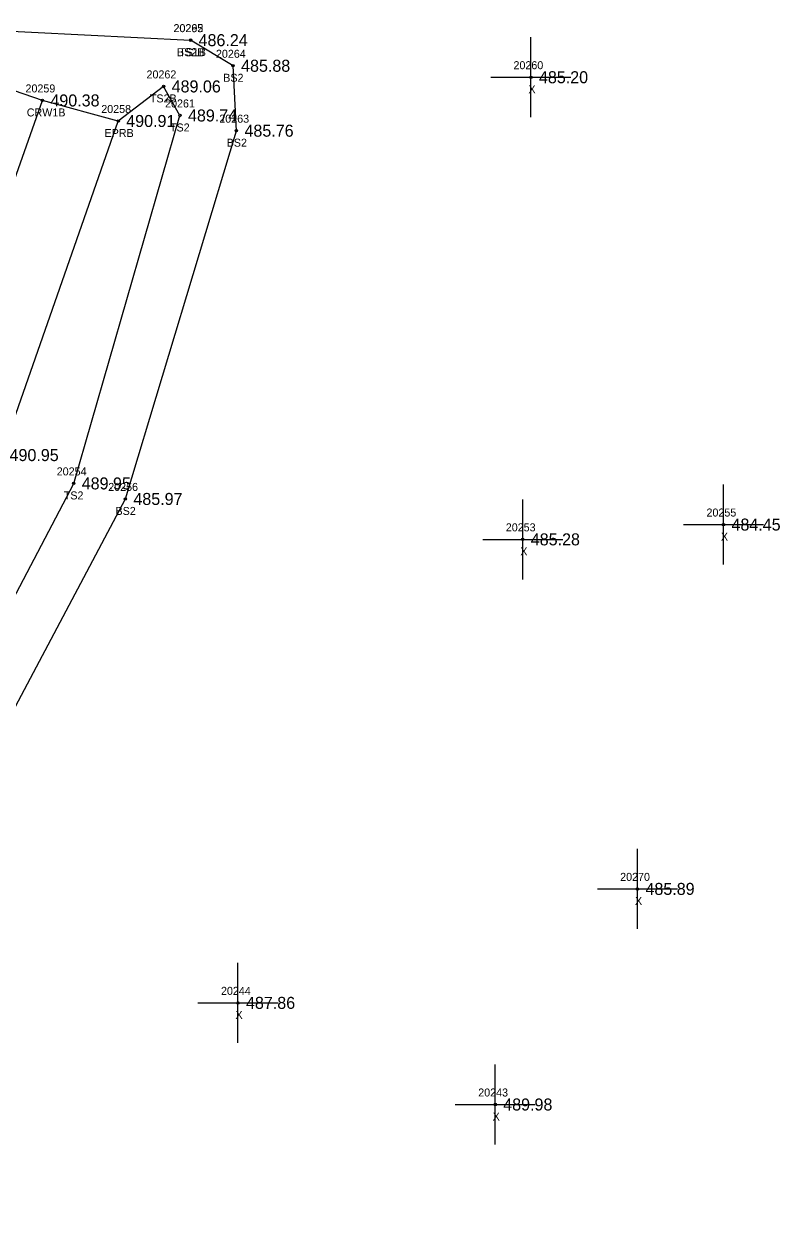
# Model space of a CAD drawing. Extents: x 1649406 to 1650436, y 896752 to 898178.
# Drawn here: x 1649874.8 to 1649969.2, y 897267.9 to 897418.2 of the extents above; entities that cross this region are included whole.
import ezdxf

# ---------------------------------------------------------------- set-up
doc = ezdxf.new("R2010")
doc.units = 0
for name, color, linetype in [('RD_DTM_BkLn1', 7, 'Continuous'), ('RD_DTM_BkLn2', 7, 'Continuous'), ('RD_DTM_BkLn_txCode', 7, 'Continuous'), ('RD_EX_Misc', 7, 'Continuous'), ('RD_EX_Misc_txCode', 7, 'Continuous'), ('RD_EX_Road', 7, 'Continuous'), ('RD_EX_Road_txCode', 7, 'Continuous'), ('RD_EX_TX_Misc_ELEV', 7, 'Continuous'), ('RD_EX_TX_Road_ELEV', 7, 'Continuous'), ('RD_HC_Survey_ELEV', 7, 'Continuous'), ('RD_HC_Survey_txCode', 7, 'Continuous'), ('RD_SMD_Locator', 7, 'Continuous')]:
    doc.layers.add(name, color=color, linetype=linetype)

msp = doc.modelspace()

# ---------------------------------------------------------------- linework, layer by layer
at = {"layer": 'RD_DTM_BkLn1'}
msp.add_lwpolyline([(1649466.79, 896799.14), (1649494.97, 896834.25), (1649557.53, 896909.97), (1649590.88, 896950.41), (1649622.36, 896988.16), (1649622.36, 896988.48), (1649654.33, 897027.92), (1649685.38, 897067.52), (1649715.96, 897107.48), (1649743.64, 897146.32), (1649771.01, 897187.23), (1649797.64, 897230.08), (1649820.89, 897273.98), (1649842.91, 897321.22), (1649862.74, 897368.05), (1649877.08, 897408.66)], dxfattribs=at)
at = {"layer": 'RD_DTM_BkLn2'}
for points in [[(1649711.48, 897127.33), (1649731.83, 897154.08), (1649758, 897194.49), (1649783.81, 897237.31), (1649806.95, 897282.89), (1649830.65, 897328.8), (1649845.62, 897375.19), (1649854.76, 897409.92), (1649862.43, 897417.84), (1649895.58, 897416.19)], [(1649852.52, 897290.54), (1649862.96, 897312.65), (1649887.44, 897358.87), (1649901.31, 897404.88), (1649900.89, 897412.99), (1649895.58, 897416.19)], [(1649843.51, 897289.97), (1649857.2, 897315.44), (1649880.99, 897360.81), (1649894.26, 897406.78), (1649892.22, 897410.41)]]:
    msp.add_lwpolyline(points, dxfattribs=at)
at = {"layer": 'RD_EX_Misc'}
for p, q in [((1649938.08, 897406.56), (1649938.08, 897416.56)), ((1649933.08, 897411.56), (1649943.08, 897411.56)), ((1649962.12, 897350.67), (1649962.12, 897360.67)), ((1649937.06, 897348.82), (1649937.06, 897358.82)), ((1649957.12, 897355.67), (1649967.12, 897355.67)), ((1649932.06, 897353.82), (1649942.06, 897353.82)), ((1649951.38, 897305.15), (1649951.38, 897315.15)), ((1649946.38, 897310.15), (1649956.38, 897310.15)), ((1649901.5, 897290.91), (1649901.5, 897300.91)), ((1649896.5, 897295.91), (1649906.5, 897295.91)), ((1649933.62, 897278.21), (1649933.62, 897288.21)), ((1649928.62, 897283.21), (1649938.62, 897283.21))]:
    msp.add_line(p, q, dxfattribs=at)
at = {"layer": 'RD_EX_Road'}
for points in [[(1649892.22, 897410.41), (1649886.55, 897406.09), (1649877.08, 897408.66), (1649867.51, 897411.96)], [(1649474.75, 896792.65), (1649502.78, 896827.35), (1649565.2, 896903.92), (1649598.28, 896943.71), (1649629.8, 896982.26), (1649667.92, 897029.33), (1649693.13, 897061.44), (1649723.58, 897101.84), (1649752.37, 897141.09), (1649779.72, 897182.3), (1649806.12, 897225.84), (1649830.13, 897270.79), (1649852.39, 897317.43), (1649871.98, 897364.35), (1649886.55, 897406.09)]]:
    msp.add_lwpolyline(points, dxfattribs=at)
at = {"layer": 'RD_SMD_Locator'}
for centre in [(1649895.58, 897416.19), (1649895.58, 897416.19), (1649900.89, 897412.99), (1649892.22, 897410.41), (1649938.08, 897411.56), (1649877.08, 897408.66), (1649886.55, 897406.09), (1649894.26, 897406.78), (1649901.31, 897404.88), (1649880.99, 897360.81), (1649887.44, 897358.87), (1649962.12, 897355.67), (1649937.06, 897353.82), (1649951.38, 897310.15), (1649901.5, 897295.91), (1649933.62, 897283.21)]:
    msp.add_circle(centre, 0.15, dxfattribs=at)

# ---------------------------------------------------------------- texts
at = {"layer": 'RD_DTM_BkLn_txCode'}
for s, p in [('20265', (1649893.44, 897417.19)), ('20292', (1649893.46, 897417.19)), ('BS2B', (1649893.88, 897414.19)), ('TS1B', (1649894.15, 897414.19)), ('20264', (1649898.75, 897413.99)), ('20262', (1649890.08, 897411.41)), ('BS2', (1649899.66, 897410.99)), ('TS2B', (1649890.5, 897408.41)), ('20261', (1649892.4, 897407.78)), ('20263', (1649899.17, 897405.88)), ('TS2', (1649893.01, 897404.78)), ('BS2', (1649900.09, 897402.88)), ('20254', (1649878.87, 897361.81)), ('20256', (1649885.3, 897359.87)), ('TS2', (1649879.75, 897358.81)), ('BS2', (1649886.21, 897356.87))]:
    msp.add_text(s, height=1, dxfattribs=at).set_placement(p)
at = {"layer": 'RD_EX_Misc_txCode'}
for s, p in [('20260', (1649935.9, 897412.56)), ('X', (1649937.77, 897409.56)), ('20255', (1649960, 897356.67)), ('20253', (1649934.94, 897354.82)), ('X', (1649961.8, 897353.67)), ('X', (1649936.75, 897351.82)), ('20270', (1649949.22, 897311.15)), ('X', (1649951.07, 897308.15)), ('20244', (1649899.38, 897296.91)), ('X', (1649901.19, 897293.91)), ('20243', (1649931.5, 897284.21)), ('X', (1649933.3, 897281.21))]:
    msp.add_text(s, height=1, dxfattribs=at).set_placement(p)
at = {"layer": 'RD_EX_Road_txCode'}
for s, p in [('20258', (1649884.43, 897407.09)), ('EPRB', (1649884.84, 897404.09))]:
    msp.add_text(s, height=1, dxfattribs=at).set_placement(p)
at = {"layer": 'RD_EX_TX_Misc_ELEV'}
for s, p in [('486.24', (1649896.58, 897415.44)), ('486.24', (1649896.58, 897415.44)), ('485.88', (1649901.89, 897412.24)), ('485.20', (1649939.08, 897410.81)), ('489.06', (1649893.22, 897409.66)), ('489.74', (1649895.26, 897406.03)), ('485.76', (1649902.31, 897404.13)), ('489.95', (1649881.99, 897360.06)), ('485.97', (1649888.44, 897358.12)), ('484.45', (1649963.12, 897354.92)), ('485.28', (1649938.06, 897353.07)), ('485.89', (1649952.38, 897309.4)), ('487.86', (1649902.5, 897295.16)), ('489.98', (1649934.62, 897282.46))]:
    msp.add_text(s, height=1.5, dxfattribs=at).set_placement(p)
at = {"layer": 'RD_EX_TX_Road_ELEV'}
for s, p in [('490.91', (1649887.55, 897405.34)), ('490.95', (1649872.98, 897363.6))]:
    msp.add_text(s, height=1.5, dxfattribs=at).set_placement(p)
at = {"layer": 'RD_HC_Survey_ELEV'}
msp.add_text('490.38', height=1.5, dxfattribs=at).set_placement((1649878.08, 897407.91))
at = {"layer": 'RD_HC_Survey_txCode'}
for s, p in [('20259', (1649874.97, 897409.66)), ('CRW1B', (1649875.13, 897406.66))]:
    msp.add_text(s, height=1, dxfattribs=at).set_placement(p)

doc.saveas('drawing.dxf')
